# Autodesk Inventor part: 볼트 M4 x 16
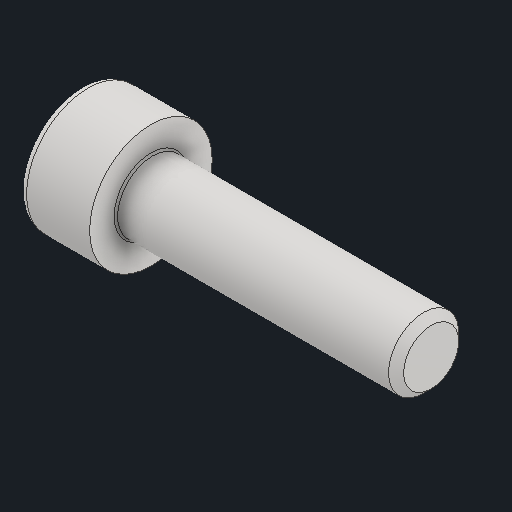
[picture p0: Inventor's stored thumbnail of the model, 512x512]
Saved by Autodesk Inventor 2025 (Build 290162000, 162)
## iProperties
Created: 2025-08
Part Number: 볼트 M4 x 16
Material: 스테인리스강
Description: 6각 소켓 머리 캡 나사
Document SubType Name: Modeling
Designer: infra005
Mass: 2.70334 g
Surface Area: 3.81118 cm^2
Volume: 0.334572 cm^3
Density: 8.08 g/cm^3
Appearance: 기본값
Author: jhkim
Sending System: Autodesk Inventor 2026
Preprocessor: ST-DEVELOPER v20.1
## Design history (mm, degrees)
feature "Solid1"
node "솔리드1"
